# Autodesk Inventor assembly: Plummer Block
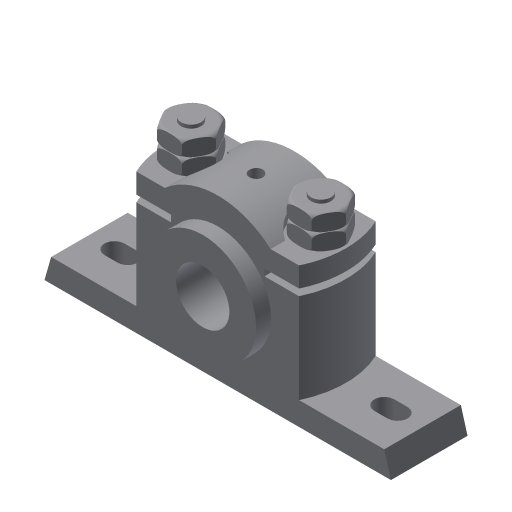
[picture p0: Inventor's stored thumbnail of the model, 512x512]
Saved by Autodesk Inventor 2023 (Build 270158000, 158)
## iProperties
Created: 2011-07
Part Number: Plummer Block
Document SubType Name: Assembly
Designer: CadCim
Author: CadCim
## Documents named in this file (7)
- D:\PROJECTS\Project 2022\Autodesk Inventor For Professional 2023\RESOURCES INVENTOR 2023\RESOURCES INVENTOR 2023\Inventor_2023_Part\Inventor_2023_Part\c11_Inv_2023_prt\c11_Inv_2023_prt\fig 11-40 through 11-45\Plummer Block.iam
- D:\PROJECTS\Project 2022\Autodesk Inventor For Professional 2023\RESOURCES INVENTOR 2023\RESOURCES INVENTOR 2023\Inventor_2023_Part\Inventor_2023_Part\c11_Inv_2023_prt\c11_Inv_2023_prt\fig 11-40 through 11-45\Casting.ipt
- D:\PROJECTS\Project 2022\Autodesk Inventor For Professional 2023\RESOURCES INVENTOR 2023\RESOURCES INVENTOR 2023\Inventor_2023_Part\Inventor_2023_Part\c11_Inv_2023_prt\c11_Inv_2023_prt\fig 11-40 through 11-45\Brasses.ipt
- D:\PROJECTS\Project 2022\Autodesk Inventor For Professional 2023\RESOURCES INVENTOR 2023\RESOURCES INVENTOR 2023\Inventor_2023_Part\Inventor_2023_Part\c11_Inv_2023_prt\c11_Inv_2023_prt\fig 11-40 through 11-45\Cap.ipt
- D:\PROJECTS\Project 2022\Autodesk Inventor For Professional 2023\RESOURCES INVENTOR 2023\RESOURCES INVENTOR 2023\Inventor_2023_Part\Inventor_2023_Part\c11_Inv_2023_prt\c11_Inv_2023_prt\fig 11-40 through 11-45\Bolt.ipt
- D:\PROJECTS\Project 2022\Autodesk Inventor For Professional 2023\RESOURCES INVENTOR 2023\RESOURCES INVENTOR 2023\Inventor_2023_Part\Inventor_2023_Part\c11_Inv_2023_prt\c11_Inv_2023_prt\fig 11-40 through 11-45\Nut.ipt
- D:\PROJECTS\Project 2022\Autodesk Inventor For Professional 2023\RESOURCES INVENTOR 2023\RESOURCES INVENTOR 2023\Inventor_2023_Part\Inventor_2023_Part\c11_Inv_2023_prt\c11_Inv_2023_prt\fig 11-40 through 11-45\Lock Nut.ipt
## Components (9 placed, 6 different names)
1. Casting:1 — Mate:1, Mate:2, Insert:1, Insert:2, Angle:1, Angle:2
2. Brasses:1 — Mate:1, Mate:2, Mate:3, Mate:4
3. Cap:1 — Mate:3, Mate:4, Insert:3, Insert:4
4. Bolt:1 — Insert:1, Angle:1
5. Bolt:2 — Insert:2, Angle:2
6. Nut:1 — Insert:3, Insert:6
7. Nut:2 — Insert:4, Insert:5
8. Lock Nut:1 — Insert:6
9. Lock Nut:2 — Insert:5
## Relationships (12: Insert 6, Mate 4, Angle 2)
- Mate:1: Casting:1 ↔ Brasses:1
- Mate:2: Casting:1 ↔ Brasses:1
- Mate:3: Brasses:1 ↔ Cap:1
- Mate:4: Brasses:1 ↔ Cap:1
- Insert:1: Casting:1 ↔ Bolt:1
- Insert:2: Casting:1 ↔ Bolt:2
- Angle:1: Casting:1 ↔ Bolt:1
- Angle:2: Casting:1 ↔ Bolt:2
- Insert:3: Cap:1 ↔ Nut:1
- Insert:4: Cap:1 ↔ Nut:2
- Insert:5: Nut:2 ↔ Lock Nut:2
- Insert:6: Nut:1 ↔ Lock Nut:1
